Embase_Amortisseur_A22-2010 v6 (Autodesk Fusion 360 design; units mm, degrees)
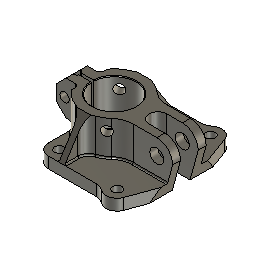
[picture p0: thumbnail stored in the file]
sketch "Esquisse1" plane through (0, 0, 0) normal (0, 0, 1) x axis (1, 0, 0)
  line L1 (48.5697, -38) -> (-17.9303, -38)
  line L2 (-17.9303, 38) -> (48.5697, 38)
  line L3 (-17.9303, -38) -> (-17.9303, 38)
  line L4 (-17.9303, 0) -> (48.5697, 0)
  line L5 (-9.8703, 29.94) -> (-9.8703, -29.94)
  line L6 (36.0401, 33.89) -> (36.0401, -33.89)
  line L7 (36.0401, -33.89) -> (-9.8703, -29.94)
  line L8 (36.0401, 33.89) -> (-9.8703, 29.94)
  line L9 (31.775, -6.4) -> (48.5697, -6.4)
  line L10 (48.5697, 6.4) -> (31.775, 6.4)
  line L11 (-19.6803, 7.7) -> (-19.6803, -7.7)
  line L12 (48.5697, -6.4) -> (48.5697, -38)
  line L13 (48.5697, 38) -> (48.5697, 6.4)
  line L14 (-10.1446, -33.1282) -> (-9.8703, -29.94)
  line L15 (-13.0585, -29.6657) -> (-9.8703, -29.94)
  line L16 (-9.8703, -38) -> (-9.8703, -29.94)
  line L17 (-17.9303, -29.94) -> (-9.8703, -29.94)
  line L18 (0, 0) -> (-9.8703, -29.94)
  line L19 (0.3032, 0) -> (36.0401, -33.89)
  line L20 (-17.9303, -8.7596) -> (-19.6803, -7.7)
  line L21 (-17.9303, 8.7596) -> (-19.6803, 7.7)
  line L22 (43.6141, 36.6467) -> (48.5697, 23.031)
  line L23 (43.6141, -36.6467) -> (48.5697, -23.031)
  line L24 (-19.6803, 1) -> (-15.6932, 1)
  line L25 (-19.6803, -1) -> (-15.6932, -1)
  circle C1 centre (0, 0) radius 15.725
  circle C2 centre (-9.8703, 29.94) radius 3.2
  circle C3 centre (-9.8703, -29.94) radius 3.2
  circle C4 centre (36.0401, 33.89) radius 3.2
  circle C5 centre (36.0401, -33.89) radius 3.2
  circle C6 centre (36.0401, -33.89) radius 8.06
  circle C7 centre (36.0401, 33.89) radius 8.06
  arc A1 centre (31.775, 0) radius 6.4 clockwise from (31.775, -6.4) to (31.775, 6.4)
  circle C8 centre (-9.8703, -29.94) radius 8.06
  circle C9 centre (-9.8703, 29.94) radius 8.06
  point P1 (0, 0)
  point P2 (0, 0)
  point P8 (-17.9303, 0)
  point P10 (-9.8703, 29.94)
  point P11 (-9.8703, 29.94)
  point P9 (-9.8703, -29.94)
  point P12 (-9.8703, -29.94)
  point P14 (36.0401, 33.89)
  point P15 (36.0401, 33.89)
  point P13 (36.0401, -33.89)
  point P16 (36.0401, -33.89)
  point P17 (-9.8703, -29.94)
  point P18 (36.0401, -33.89)
  point P19 (-9.8703, 29.94)
  point P20 (36.0401, 33.89)
  point P22 (48.5697, 6.4)
  point P25 (-19.6803, 0)
  point P26 (36.0401, -33.89)
  point P27 (36.0401, 33.89)
  point P28 (31.775, 0)
  point P31 (25.375, 0)
  point P32 (15.725, 0)
  point P7 (48.5697, 0)
  point P33 (-10.1446, -33.1282)
  point P34 (-13.0585, -29.6657)
  point P35 (-9.8703, -26.74)
  point P36 (-9.8703, 26.74)
  point P37 (36.0401, -30.69)
  point P38 (36.0401, 30.69)
  point P39 (-9.8703, -29.94)
  point P40 (-9.8703, -38)
  point P41 (-9.8703, -29.94)
  point P42 (-17.9303, -29.94)
  point P43 (-9.8703, -29.94)
  point P45 (-9.8703, -29.94)
  point P46 (0, 0)
  point P47 (-8.8684, -26.9009)
  point P48 (-4.9234, -14.9344)
  point P49 (36.0401, -33.89)
  point P50 (0.3032, 0)
  point P51 (11.5528, -10.6682)
  point P52 (33.7182, -31.6881)
  point P53 (-17.9303, -8.7596)
  point P54 (-17.9303, 8.7596)
  point P55 (48.5697, 23.031)
  point P56 (43.6141, 36.6467)
  point P57 (48.5697, -23.031)
  point P58 (43.6141, -36.6467)
  point P59 (-15.6932, 1)
  point P60 (-19.6803, 1)
  point P61 (-15.6932, -1)
  point P62 (-19.6803, -1)
  point P23 (-19.6803, -7.7)
  point P24 (-19.6803, 7.7)
  coincident P1 P2
  horizontal L1
  vertical L12
  horizontal L2
  vertical L3
  midpoint L3 P8
  coincident P2 L4
  perpendicular L2 L5
  coincident P10 P11
  coincident P9 P12
  perpendicular L4 L6
  coincident P14 P15
  coincident P13 P16
  symmetric L4 C4 C5
  symmetric L4 C2 C3
  coincident P12 P17
  coincident P16 P18
  coincident P11 P19
  coincident P15 P20
  perpendicular L6 L9
  coincident P22 L12
  perpendicular L10 L12
  vertical L11
  midpoint L11 P25
  coincident L4 P25
  coincident P13 P26
  coincident P14 P27
  equal C6 C7
  equal C3 C5
  coincident L4 P28
  tangent L10 A1
  midpoint A1 P31
  coincident C1 P32
  coincident L4 P32
  tangent L9 A1
  collinear L12 L13
  coincident P7 L12
  coincident C3 P33
  perpendicular L7 L14
  coincident C3 P34
  perpendicular L14 L15
  coincident C3 P35
  coincident L5 P35
  coincident C2 P36
  coincident L5 P36
  coincident C5 P37
  coincident L6 P37
  coincident C4 P38
  coincident L6 P38
  coincident P12 P39
  coincident L1 P40
  perpendicular L1 L16
  coincident P12 P41
  coincident L3 P42
  perpendicular L3 L17
  equal L16 L17
  concentric C3 C8
  coincident P42 C8
  concentric C2 C9
  tangent L2 C9
  equal C6 C8
  coincident P43 P45
  coincident P2 P46
  coincident C3 P47
  coincident L18 P47
  coincident C1 P48
  coincident L18 P48
  coincident P16 P49
  coincident L4 P50
  coincident C1 P51
  coincident L19 P51
  coincident L19 P52
  coincident C5 P52
  coincident L3 P53
  coincident L3 P54
  symmetric L4 L20 L21
  coincident L13 P55
  coincident C7 P56
  tangent C7 L22
  coincident L12 P57
  coincident C6 P58
  tangent C6 L23
  symmetric L4 L22 L23
  coincident C1 P59
  coincident L11 P60
  perpendicular L11 L24
  coincident C1 P61
  coincident L11 P62
  perpendicular L11 L25
  symmetric L4 L24 L25
  dimension "d1" distance L1 L2 = 76
  dimension "d2" diameter C3 = 6.4
  dimension "d3" distance L9 L10 = 12.8
  dimension "d7" distance P31 P32 = 9.65
  dimension "d8" distance L3 L12 = 66.5
  dimension "d9" diameter C1 = 31.45
  dimension "d12" distance P13 P14 = 67.78
  dimension "d13" distance P9 P10 = 59.88
  dimension "d14" distance P17 P18 = 46.08
  dimension "d16" distance L1 P12 = 8.06
  dimension "d17" distance L3 L11 = 1.75
  dimension "d18" distance P47 P48 = 12.6
  dimension "d21" angle L1 L23 = 110
  dimension "d24" distance L24 L25 = 2
  dimension "d67" distance P23 P24 = 15.4
extrude "Extrusion1" new body sketch "Esquisse1" profile of C1 L1 L13 L2 L3 C2 C3 C4 C5 L9 L10 L11 C6 C7 A1 C8 C9 L20 L21 L22 L23 L24 L25 along normal blind 8.1
sketch "Esquisse2" plane through (0, 0, 8.1) normal (0, 0, 1) x axis (-1, 0, 0)
  line L1 (19.6803, 1) -> (15.6932, 1)
  line L2 (19.6803, 7.7) -> (19.6803, 1)
  line L3 (17.9303, 8.7596) -> (19.6803, 7.7)
  line L4 (17.9303, 29.94) -> (17.9303, 8.7596)
  line L5 (-29.1068, 38) -> (9.8703, 38)
  line L6 (-48.5697, 23.031) -> (-43.6141, 36.6467)
  line L7 (-48.5697, 6.4) -> (-48.5697, 23.031)
  line L8 (-31.775, 6.4) -> (-48.5697, 6.4)
  line L9 (-48.5697, -6.4) -> (-31.775, -6.4)
  line L10 (-48.5697, -23.031) -> (-48.5697, -6.4)
  line L11 (-43.6141, -36.6467) -> (-48.5697, -23.031)
  line L12 (9.8703, -38) -> (-29.1068, -38)
  line L13 (17.9303, -8.7596) -> (17.9303, -29.94)
  line L14 (19.6803, -7.7) -> (17.9303, -8.7596)
  line L15 (19.6803, -1) -> (19.6803, -7.7)
  line L16 (15.6932, -1) -> (19.6803, -1)
  line L17 (-54.485, -12.15) -> (-18.4005, -12.15)
  line L18 (-54.485, 12.15) -> (-54.485, -12.15)
  line L19 (-18.4005, 12.15) -> (-54.485, 12.15)
  line L20 (-18.4005, -12.15) -> (-18.4005, 12.15)
  line L21 (2.05, -21.9545) -> (-2.05, -21.9545)
  line L22 (2.05, -38) -> (2.05, -21.9545)
  line L23 (-2.05, -38) -> (2.05, -38)
  line L24 (-2.05, -21.9545) -> (-2.05, -38)
  line L25 (-2.5, 0) -> (-20, 0)
  line L26 (2.05, 38) -> (2.05, 21.9545)
  line L27 (-2.05, 21.9545) -> (-2.05, 38)
  line L28 (-2.05, 38) -> (2.05, 38)
  line L29 (-43.005, 12.15) -> (-43.005, -12.15)
  line L30 (34.475, -7.7) -> (20.6619, -7.7)
  line L31 (34.475, 7.7) -> (34.475, -7.7)
  line L32 (20.6619, 7.7) -> (34.475, 7.7)
  line L33 (20.6619, -7.7) -> (20.6619, 7.7)
  line L34 (20.6619, -2.7) -> (34.475, -2.7)
  line L35 (20.6619, 2.7) -> (34.475, 2.7)
  line L36 (20.6619, 0) -> (34.475, 0)
  line L37 (28.265, -2.7) -> (28.265, 2.7)
  line L38 (24.667, -1) -> (19.6803, -1)
  line L39 (24.667, 1) -> (19.6803, 1)
  line L40 (15.6932, -1) -> (19.6803, -1)
  line L41 (19.6803, 1) -> (15.6932, 1)
  line L42 (-54.485, 6.4) -> (-48.5697, 6.4)
  line L43 (-54.485, -6.4) -> (-48.5697, -6.4)
  circle C1 centre (-36.0401, -33.89) radius 3.2
  circle C2 centre (-36.0401, 33.89) radius 3.2
  circle C3 centre (9.8703, 29.94) radius 3.2
  circle C4 centre (9.8703, -29.94) radius 3.2
  arc A1 centre (0, 0) radius 15.725 clockwise from (15.6932, -1) to (15.6932, 1)
  arc A2 centre (9.8703, 29.94) radius 8.06 clockwise from (9.8703, 38) to (17.9303, 29.94)
  arc A3 centre (-36.0401, 33.89) radius 8.06 clockwise from (-43.6141, 36.6467) to (-29.1068, 38)
  arc A4 centre (-31.775, 0) radius 6.4 clockwise from (-31.775, 6.4) to (-31.775, -6.4)
  arc A5 centre (-36.0401, -33.89) radius 8.06 clockwise from (-29.1068, -38) to (-43.6141, -36.6467)
  arc A6 centre (9.8703, -29.94) radius 8.06 clockwise from (17.9303, -29.94) to (9.8703, -38)
  circle C5 centre (0, 0) radius 22.05
  arc A7 centre (27.175, 0) radius 2.7 clockwise from (27.175, -2.7) to (27.175, 2.7)
  arc A8 centre (0, 0) radius 15.725 clockwise from (15.6932, -1) to (15.6932, 1)
  point P1 (0, 0)
  point P30 (0, 0)
  point P31 (-18.4005, -12.15)
  point P34 (-18.4005, 12.15)
  point P37 (2.05, -38)
  point P35 (-2.05, -21.9545)
  point P36 (2.05, -21.9545)
  point P44 (-2.05, 21.9545)
  point P41 (2.05, 21.9545)
  point P42 (2.05, 38)
  point P38 (-2.05, -38)
  point P43 (-2.05, 38)
  point P45 (-43.005, -12.15)
  point P46 (-43.005, 12.15)
  point P47 (-15.725, 0)
  point P48 (20.6619, -7.7)
  point P51 (20.6619, 7.7)
  point P52 (34.475, -2.7)
  point P53 (20.6619, -2.7)
  point P54 (34.475, 2.7)
  point P55 (20.6619, 2.7)
  point P56 (34.475, 0)
  point P57 (20.6619, 0)
  point P58 (27.175, 0)
  point P59 (27.175, -2.7)
  point P60 (27.175, 2.7)
  point P61 (24.475, 0)
  point P62 (28.265, 2.7)
  point P63 (28.265, -2.7)
  point P29 (19.6803, -1)
  point P64 (19.6803, -1)
  point P65 (24.667, -1)
  point P9 (19.6803, 1)
  point P66 (19.6803, 1)
  point P67 (24.667, 1)
  point P17 (-48.5697, 6.4)
  point P73 (-48.5697, 6.4)
  point P74 (-54.485, 6.4)
  point P21 (-48.5697, -6.4)
  point P75 (-48.5697, -6.4)
  point P76 (-54.485, -6.4)
  point P32 (-54.485, -12.15)
  point P33 (-54.485, 12.15)
  coincident P1 P30
  horizontal L17
  vertical L18
  horizontal L19
  vertical L20
  coincident C5 P31
  coincident C5 P34
  horizontal L21
  vertical L22
  horizontal L23
  vertical L24
  coincident L12 P37
  coincident C5 P35
  coincident C5 P36
  symmetric P35 L25 P44
  symmetric P36 L25 P41
  symmetric P37 L25 P42
  symmetric P38 L25 P43
  coincident L17 P45
  coincident L19 P46
  perpendicular L19 L29
  midpoint A1 P47
  horizontal L30
  vertical L31
  horizontal L32
  vertical L33
  coincident C5 P48
  coincident C5 P51
  coincident L31 P52
  coincident L33 P53
  perpendicular L33 L34
  coincident L31 P54
  coincident L33 P55
  perpendicular L33 L35
  midpoint L31 P56
  midpoint L33 P57
  coincident L36 P58
  tangent L34 A7
  symmetric L34 L35 L36
  coincident L34 P59
  coincident L35 P60
  midpoint A7 P61
  coincident L35 P62
  coincident L34 P63
  perpendicular L34 L37
  coincident P29 P64
  coincident A7 P65
  perpendicular L15 L38
  coincident P9 P66
  coincident A7 P67
  perpendicular L33 L39
  coincident P17 P73
  coincident L18 P74
  perpendicular L18 L42
  coincident P21 P75
  coincident L18 P76
  perpendicular L18 L43
  dimension "d25" diameter C5 = 44.1
  dimension "d26" distance P32 P33 = 24.3
  dimension "d27" distance P37 P38 = 4.1
  dimension "d28" distance L29 P47 = 27.28
  dimension "d30" distance L34 L35 = 5.4
  dimension "d31" distance P56 P61 = 10
  dimension "d32" distance L31 L37 = 6.21
  dimension "d33" distance L30 L34 = 5
  dimension "d34" distance L29 L37 = 71.27
  dimension "d52" distance L18 L29 = 11.48
extrude "Extrusion2" add sketch "Esquisse2" profile of A1 L1 L2 L3 L4 L5 L7 L8 A4 L9 L10 L12 L13 L14 L15 L16 C5 L17 L18 L19 L20 L21 L22 L23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 along normal blind 25 (= "33 mm - 8 mm")
sketch "Esquisse3" plane through (0, -7.7, 0) normal (0, -1, 0) x axis (1, 0, 0)
  line L1 (-20.6619, 8.1) -> (-34.475, 8.1)
  line L2 (-20.6619, 33.1) -> (-20.6619, 8.1)
  line L3 (-34.475, 33.1) -> (-20.6619, 33.1)
  line L4 (-34.475, 8.1) -> (-34.475, 33.1)
  line L5 (-28.265, 33.1) -> (-28.265, 8.1)
  line L6 (-34.475, 25.85) -> (-27.225, 33.1)
  line L7 (-34.475, 15.35) -> (-27.225, 8.1)
  line L8 (-34.475, 20.6) -> (-28.265, 20.6)
  line L9 (-19.6803, 8.1) -> (-19.6803, 0)
  line L10 (-20.6619, 8.1) -> (-17.9303, 8.1)
  line L11 (-34.475, 8.1) -> (-20.6619, 8.1)
  line L12 (-27.175, 8.1) -> (-34.475, 8.1)
  line L13 (-27.175, 8.1) -> (-24.667, 8.1)
  line L14 (-19.6803, 8.1) -> (-24.667, 8.1)
  line L15 (-17.9303, 8.1) -> (-19.6803, 8.1)
  line L16 (-20.6619, 8.1) -> (-34.475, 8.1)
  line L17 (-19.6803, 1.1) -> (-26.6803, 1.1)
  line L18 (-26.6803, 8.1) -> (-26.6803, 1.1)
  circle C1 centre (-28.265, 20.6) radius 3.125
  circle C2 centre (-26.6803, 1.1) radius 7
  point P6 (-28.265, 8.1)
  point P7 (-28.265, 8.1)
  point P8 (-28.265, 33.1)
  point P9 (-28.265, 20.6)
  point P10 (-27.225, 33.1)
  point P11 (-34.475, 25.85)
  point P12 (-27.225, 8.1)
  point P13 (-34.475, 15.35)
  point P14 (-28.265, 20.6)
  point P15 (-34.475, 20.6)
  point P24 (-26.6803, 1.1)
  point P27 (-26.6803, 1.1)
  point P28 (-19.6803, 1.1)
  point P29 (-26.6803, 1.1)
  point P30 (-26.6803, 8.1)
  coincident P6 P7
  coincident L3 P8
  perpendicular L3 L5
  midpoint L5 P9
  coincident L3 P10
  coincident L4 P11
  coincident L1 P12
  coincident L4 P13
  coincident P9 P14
  midpoint L4 P15
  symmetric L6 L7 L8
  tangent L9 C2
  tangent C2 L16
  coincident P24 P27
  coincident L9 P28
  coincident C2 P28
  perpendicular L9 L17
  coincident P24 P29
  coincident L11 P30
  coincident C2 P30
  dimension "d37" diameter C1 = 6.25
  dimension "d38" angle L3 L6 = 45
  dimension "d39" distance P11 P13 = 10.5
  dimension "d40" diameter C2 = 14
extrude "Extrusion3" cut sketch "Esquisse3" profile of L1 L3 L4 C1 L6 L7 L11 L12 L16 no distance stored
extrude "Extrusion4" add sketch "Esquisse3" profile of L1 L9 L10 L11 L13 L14 C2 L16 to an object
extrude "Extrusion5" cut of existing geometry no distance stored
work_plane "Plan de construction" RotateAngle 35
sketch "Esquisse4" plane through (0, 0, 0) normal (-0.5736, 0.8192, 0) x axis (0, 0, 1)
  line L1 (33.1, -26.718) -> (33.1, -23.8501)
  line L2 (33.1, -21.3417) -> (33.1, -26.718)
  line L3 (33.1, -14.2718) -> (33.1, -22.05)
  line L4 (33.1, -23.4752) -> (33.1, -14.2718)
  line L5 (33.1, -20.1166) -> (33.1, -23.4752)
  line L6 (33.1, -10.9133) -> (33.1, -20.1166)
  line L7 (33.1, 8.1039) -> (33.1, -10.9133)
  line L8 (33.1, 37.6625) -> (33.1, 8.1039)
  line L9 (33.1, 40.9606) -> (33.1, 37.6625)
  line L10 (33.1, 22.3577) -> (33.1, 40.9606)
  line L11 (33.1, 19.6286) -> (33.1, 29.6994)
  line L12 (33.1, 48.3024) -> (33.1, 29.6994)
  line L13 (33.1, 51.6005) -> (33.1, 48.3024)
  line L14 (33.1, 22.0418) -> (33.1, 51.6005)
  line L15 (33.1, 22.05) -> (33.1, 14.2718)
  line L16 (33.1, 23.4752) -> (33.1, 14.2718)
  line L17 (33.1, 20.1166) -> (33.1, 23.4752)
  line L18 (33.1, 10.9133) -> (33.1, 20.1166)
  line L19 (33.1, 10.9133) -> (33.1, -12.5087)
  line L20 (33.1, -17.8849) -> (33.1, -12.5087)
  line L21 (33.1, -20.7528) -> (33.1, -17.8849)
  line L22 (33.1, -20.7118) -> (33.1, -20.7528)
  line L23 (33.1, -20.7118) -> (33.1, -19.5605)
  line L24 (33.1, -12.2815) -> (33.1, -19.6325)
  line L25 (33.1, -15.725) -> (33.1, 15.725)
  line L26 (33.1, -20.7796) -> (33.1, -13.4287)
  line L27 (33.1, -23.8091) -> (33.1, -20.7796)
  line L28 (33.1, -23.8501) -> (33.1, -23.8091)
  line L29 (24.99, 0) -> (33.1, 0)
  circle C1 centre (24.99, 0) radius 3.3782
  point P36 (33.1, 0)
  point P37 (24.99, 0)
  point P38 (24.99, 0)
  midpoint L25 P36
  perpendicular L7 L29
  coincident P37 P38
  dimension "d46" distance P36 P37 = 8.11
  dimension "d47" diameter C1 = 6.7564
extrude "Extrusion6" cut sketch "Esquisse4" profile of C1 along a picked direction no distance stored
sketch "Esquisse5" plane through (-2.05, 0, 0) normal (-1, 0, 0) x axis (0, -1, 0)
  line L1 (38, 8.1) -> (21.9545, 8.1)
  line L2 (38, 33.1) -> (38, 8.1)
  line L3 (21.9545, 33.1) -> (38, 33.1)
  line L4 (21.9545, 8.1) -> (21.9545, 33.1)
  line L5 (21.9545, 33.1) -> (38, 8.1)
  line L6 (-21.9545, 8.1) -> (-38, 8.1)
  line L7 (-21.9545, 33.1) -> (-21.9545, 8.1)
  line L8 (-38, 33.1) -> (-21.9545, 33.1)
  line L9 (-38, 8.1) -> (-38, 33.1)
  line L10 (-38, 8.1) -> (-21.9545, 33.1)
  point P3 (38, 8.1)
  point P6 (38, 8.1)
  point P5 (21.9545, 33.1)
  point P7 (21.9545, 33.1)
  point P10 (-21.9545, 33.1)
  point P12 (-21.9545, 33.1)
  point P8 (-38, 8.1)
  point P13 (-38, 8.1)
  coincident P3 P6
  coincident P5 P7
  coincident P10 P12
  coincident P8 P13
extrude "Extrusion7" cut sketch "Esquisse5" profile of L2 L3 L5 L8 L9 L10 no distance stored
sketch "Esquisse6" plane through (0, -12.15, 0) normal (0, -1, 0) x axis (1, 0, 0)
  line L1 (54.485, 8.1) -> (48.5697, 8.1)
  line L2 (54.485, 33.1) -> (54.485, 8.1)
  line L3 (18.4005, 33.1) -> (54.485, 33.1)
  line L4 (18.4005, 8.1) -> (18.4005, 33.1)
  line L5 (48.5697, 8.1) -> (18.4005, 8.1)
  line L6 (43.005, 33.1) -> (43.005, 8.1)
  line L7 (54.485, 21.62) -> (43.005, 21.62)
  line L8 (48.5697, 0) -> (54.485, 21.62)
  line L9 (48.5697, 8.1) -> (48.5697, 0)
  line L10 (48.5697, 0) -> (48.5697, 8.1)
  line L11 (54.485, 8.1) -> (48.5697, 8.1)
  line L12 (48.5697, 8.1) -> (54.485, 8.1)
  circle C1 centre (43.005, 21.62) radius 4.765
  circle C2 centre (43.005, 21.62) radius 11.48
  point P7 (43.005, 8.1)
  point P8 (43.005, 8.1)
  point P9 (43.005, 33.1)
  point P10 (43.005, 21.62)
  point P13 (43.005, 21.62)
  point P14 (54.485, 21.62)
  point P12 (48.5697, 0)
  point P15 (48.5697, 0)
  coincident P7 P8
  coincident L3 P9
  perpendicular L3 L6
  coincident L6 P10
  concentric C1 C2
  tangent L2 C2
  tangent L3 C2
  coincident P10 P13
  coincident C2 P14
  perpendicular L2 L7
  coincident P12 P15
  dimension "d51" diameter C1 = 9.53
extrude "Extrusion8" cut sketch "Esquisse6" profile of L1 L2 L3 C1 C2 L8 L11 L12 no distance stored
extrude "Extrusion9" add sketch "Esquisse6" profile of L1 L8 L9 L10 L11 L12 to an object Side2Offset 0
extrude "Extrusion10" cut sketch "Esquisse2" profile of L8 A4 L9 L18 L42 L43 no distance stored
sketch "Esquisse7" plane through (0, 0, 8.1) normal (0, 0, 1) x axis (-1, 0, 0)
  line L1 (-2.05, 38) -> (-2.05, 21.9545)
  line L2 (-29.1068, 38) -> (-2.05, 38)
  line L3 (-48.5697, 23.031) -> (-43.6141, 36.6467)
  line L4 (-50.7859, 23.031) -> (-48.5697, 23.031)
  line L5 (-50.7859, 12.15) -> (-50.7859, 23.031)
  line L6 (-18.4005, 12.15) -> (-50.7859, 12.15)
  line L7 (-48.5697, 23.031) -> (-43.6141, 36.6467)
  line L8 (-43.6141, -36.6467) -> (-48.5697, -23.031)
  line L9 (-50.7859, -16.9422) -> (-48.5697, -23.031)
  line L10 (-50.7859, -12.15) -> (-50.7859, -23.031)
  line L11 (-50.7859, -12.15) -> (-18.4005, -12.15)
  line L12 (-50.7859, -23.031) -> (-50.7859, -12.15)
  line L13 (-48.5697, -23.031) -> (-50.7859, -23.031)
  line L14 (-43.6141, -36.6467) -> (-48.5697, -23.031)
  line L15 (-2.05, -38) -> (-29.1068, -38)
  line L16 (-2.05, -21.9545) -> (-2.05, -38)
  line L17 (-50.7859, 23.031) -> (-50.7859, 12.15)
  line L18 (-50.7859, 23.031) -> (-48.5697, 23.031)
  line L19 (-50.7859, 16.9422) -> (-48.5697, 23.031)
  arc A1 centre (-36.0401, 33.89) radius 8.06 clockwise from (-43.6141, 36.6467) to (-29.1068, 38)
  arc A2 centre (0, 0) radius 22.05 clockwise from (-18.4005, 12.15) to (-2.05, 21.9545)
  circle C1 centre (-36.0401, 33.89) radius 3.2
  arc A3 centre (-36.0401, -33.89) radius 8.06 clockwise from (-29.1068, -38) to (-43.6141, -36.6467)
  arc A4 centre (0, 0) radius 22.05 clockwise from (-2.05, -21.9545) to (-18.4005, -12.15)
  circle C2 centre (-36.0401, -33.89) radius 3.2
  point P14 (-48.5697, -23.031)
  point P16 (-48.5697, -23.031)
  point P13 (-48.5697, 23.031)
  point P32 (-48.5697, 23.031)
  point P17 (-50.7859, -16.9422)
  coincident P14 P16
  coincident P13 P32
  parallel L3 L19
  coincident P17 L12
  collinear L9 L14
extrude "Extrusion11" cut sketch "Esquisse7" profile of L4 L5 L9 L10 L12 L13 L17 L18 L19 no distance stored
fillet "Congé1" radius 17
fillet "Congé2" radius 8
sketch "Esquisse8" plane through (0, 0, 0) normal (0, 0, -1) x axis (1, 0, 0)
  line L1 (-19.6803, -1) -> (-15.6932, -1)
  line L2 (-19.6803, -7.7) -> (-19.6803, -1)
  line L3 (-17.9303, -8.7596) -> (-19.6803, -7.7)
  line L4 (-17.9303, -29.94) -> (-17.9303, -8.7596)
  line L5 (29.1068, -38) -> (-9.8703, -38)
  line L6 (48.5697, -23.031) -> (43.6141, -36.6467)
  line L7 (48.5697, -6.4) -> (48.5697, -23.031)
  line L8 (31.775, -6.4) -> (48.5697, -6.4)
  line L9 (48.5697, 6.4) -> (31.775, 6.4)
  line L10 (48.5697, 23.031) -> (48.5697, 6.4)
  line L11 (43.6141, 36.6467) -> (48.5697, 23.031)
  line L12 (-9.8703, 38) -> (29.1068, 38)
  line L13 (-17.9303, 8.7596) -> (-17.9303, 29.94)
  line L14 (-19.6803, 7.7) -> (-17.9303, 8.7596)
  line L15 (-19.6803, 1) -> (-19.6803, 7.7)
  line L16 (-15.6932, 1) -> (-19.6803, 1)
  line L17 (-17.9303, -8.7596) -> (-17.9303, -7.7)
  line L18 (22.5, 0) -> (1.75, 0)
  line L19 (-19.6803, -7.7) -> (-26.6803, -7.7)
  line L20 (-17.9303, -7.7) -> (-19.6803, -7.7)
  line L21 (-20.6619, -10.4316) -> (-20.6619, -7.7)
  circle C1 centre (36.0401, -33.89) radius 3.2
  circle C2 centre (36.0401, 33.89) radius 3.2
  circle C3 centre (-9.8703, 29.94) radius 3.2
  circle C4 centre (-9.8703, -29.94) radius 3.2
  arc A1 centre (0, 0) radius 15.725 clockwise from (-15.6932, 1) to (-15.6932, -1)
  arc A2 centre (-9.8703, -29.94) radius 8.06 clockwise from (-9.8703, -38) to (-17.9303, -29.94)
  arc A3 centre (36.0401, -33.89) radius 8.06 clockwise from (43.6141, -36.6467) to (29.1068, -38)
  arc A4 centre (31.775, 0) radius 6.4 clockwise from (31.775, -6.4) to (31.775, 6.4)
  arc A5 centre (36.0401, 33.89) radius 8.06 clockwise from (29.1068, 38) to (43.6141, 36.6467)
  arc A6 centre (-9.8703, 29.94) radius 8.06 clockwise from (-17.9303, 29.94) to (-9.8703, 38)
  circle C5 centre (-20.6619, -10.4316) radius 2.7316
  circle C6 centre (-20.6619, 10.4316) radius 2.7316
  arc A7 centre (0, 0) radius 22.05 clockwise from (-17.9303, -12.8339) to (-20.6619, -7.7)
  point P11 (-17.9303, -8.7596)
  point P31 (-17.9303, -8.7596)
  point P37 (-19.6803, -7.7)
  point P38 (-19.6803, -7.7)
  point P39 (-20.6619, -7.7)
  point P42 (-20.6619, -7.7)
  point P32 (-20.6619, -10.4316)
  point P43 (-20.6619, -10.4316)
  coincident P11 P31
  tangent L17 C5
  symmetric C5 L18 C6
  coincident P37 P38
  collinear L19 L20
  perpendicular L17 L20
  tangent C5 L20
  coincident P39 P42
  coincident P32 P43
  vertical L21
extrude "Extrusion12" cut sketch "Esquisse8" profile of L2 L3 L14 L15 C5 C6 no distance stored
extrude "Extrusion13" cut of existing geometry no distance stored
extrude "Extrusion14" add of existing geometry to an object
extrude "Extrusion15" cut of existing geometry no distance stored
chamfer "Chanfrein" distance 0.5
fillet "Congé3" radius 9
fillet "Congé4" radius 1
canvas "Zone de dessin1"
canvas "Zone de dessin2"
sketch "Esquisse9" plane through (0, 0, 0) normal (0, 0, -1) x axis (1, 0, 0)
  line L1 (-19.6803, -1) -> (-16.1942, -1)
  line L2 (-19.6803, -7.8825) -> (-19.6803, -1)
  line L3 (-17.9303, -29.94) -> (-17.9303, -10.4316)
  line L4 (25.1236, -38) -> (-9.8703, -38)
  line L5 (48.5697, -23.031) -> (43.6141, -36.6467)
  line L6 (48.5697, -6.4) -> (48.5697, -23.031)
  line L7 (31.775, -6.4) -> (48.5697, -6.4)
  line L8 (48.5697, 6.4) -> (31.775, 6.4)
  line L9 (48.5697, 23.031) -> (48.5697, 6.4)
  line L10 (43.6141, 36.6467) -> (48.5697, 23.031)
  line L11 (-9.8703, 38) -> (25.1236, 38)
  line L12 (-17.9303, 10.4316) -> (-17.9303, 29.94)
  line L13 (-19.6803, 1) -> (-19.6803, 7.8825)
  line L14 (-16.1942, 1) -> (-19.6803, 1)
  circle C1 centre (36.0401, -33.89) radius 3.2
  circle C2 centre (36.0401, 33.89) radius 3.2
  circle C3 centre (-9.8703, -29.94) radius 3.2
  circle C4 centre (-9.8703, 29.94) radius 3.2
  arc A1 centre (0, 0) radius 16.225 clockwise from (-16.1942, 1) to (-16.1942, -1)
  arc A2 centre (-20.6619, -10.4316) radius 2.7316 clockwise from (-19.6803, -7.8825) to (-17.9303, -10.4316)
  arc A3 centre (-9.8703, -29.94) radius 8.06 clockwise from (-9.8703, -38) to (-17.9303, -29.94)
  arc A4 centre (25.1236, -47) radius 9 clockwise from (25.1236, -38) to (30.8826, -40.0838)
  arc A5 centre (36.0401, -33.89) radius 8.06 clockwise from (43.6141, -36.6467) to (30.8826, -40.0838)
  arc A6 centre (31.775, 0) radius 6.4 clockwise from (31.775, -6.4) to (31.775, 6.4)
  arc A7 centre (36.0401, 33.89) radius 8.06 clockwise from (30.8826, 40.0838) to (43.6141, 36.6467)
  arc A8 centre (25.1236, 47) radius 9 clockwise from (30.8826, 40.0838) to (25.1236, 38)
  arc A9 centre (-9.8703, 29.94) radius 8.06 clockwise from (-17.9303, 29.94) to (-9.8703, 38)
  arc A10 centre (-20.6619, 10.4316) radius 2.7316 clockwise from (-17.9303, 10.4316) to (-19.6803, 7.8825)
  circle C5 centre (-9.8703, 29.94) radius 3.3782
  circle C6 centre (36.0401, 33.89) radius 3.3782
  circle C7 centre (36.0401, -33.89) radius 3.3782
  circle C8 centre (-9.8703, -29.94) radius 3.3782
  concentric C4 C5
  concentric C2 C6
  concentric C1 C7
  concentric C3 C8
  equal C5 C6
  equal C6 C7
  equal C7 C8
  dimension "d77" diameter C5 = 6.7564
extrude "Extrusion16" cut sketch "Esquisse9" profile of C1 C2 C3 C4 C5 C6 C7 C8 no distance stored
sketch "Esquisse10" plane through (0, -7.7, 0) normal (0, -1, 0) x axis (1, 0, 0)
  line L1 (-20.6619, 33.1) -> (-20.6619, 4.6748)
  line L2 (-27.225, 33.1) -> (-20.6619, 33.1)
  line L3 (-34.475, 25.85) -> (-27.225, 33.1)
  line L4 (-34.475, 15.35) -> (-34.475, 25.85)
  line L5 (-27.225, 8.1) -> (-34.475, 15.35)
  line L6 (-26.6803, 8.1) -> (-27.225, 8.1)
  arc A1 centre (-26.6803, 1.1) radius 7 clockwise from (-26.6803, 8.1) to (-20.6619, 4.6748)
  circle C1 centre (-28.265, 20.6) radius 3.125
  circle C2 centre (-28.265, 20.6) radius 3.3782
  concentric C1 C2
  dimension "d79" diameter C2 = 6.7564
extrude "Extrusion17" cut sketch "Esquisse10" profile of C1 C2 no distance stored
sketch "Esquisse11" plane through (0, -12.15, 0) normal (0, -1, 0) x axis (1, 0, 0)
  line L1 (51.0595, 9.1) -> (25.9842, 9.1)
  line L2 (54.485, 21.62) -> (51.0595, 9.1)
  line L3 (25.9842, 33.1) -> (43.005, 33.1)
  line L4 (25.9842, 9.1) -> (25.9842, 33.1)
  circle C1 centre (43.005, 21.62) radius 4.765
  arc A1 centre (43.005, 21.62) radius 11.48 clockwise from (43.005, 33.1) to (54.485, 21.62)
  circle C2 centre (43.005, 21.62) radius 5.0419
  concentric C1 C2
  dimension "d81" diameter C2 = 10.0838
extrude "Extrusion18" cut sketch "Esquisse11" profile of C1 C2 no distance stored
